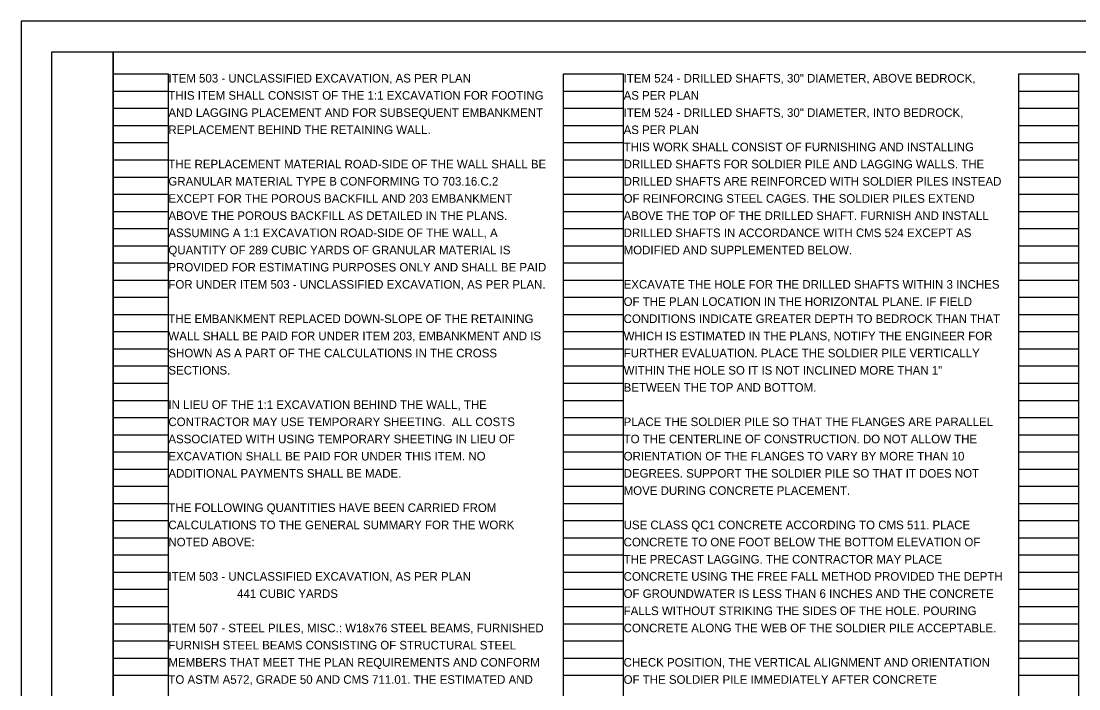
# Model space of a CAD drawing. Extents: x 0 to 34, y 0 to 22.
# Drawn here: x 0 to 17.24, y 11.12 to 22 of the extents above; entities that cross this region are included whole.
import ezdxf

# ---------------------------------------------------------------- set-up
doc = ezdxf.new("R2010")
doc.units = 0
for name, color, linetype in [('RD_P_Text', 7, 'Continuous'), ('SH_Border', 7, 'Continuous'), ('SH_Cut_Line', 7, 'Continuous'), ('SH_Data', 7, 'Continuous')]:
    doc.layers.add(name, color=color, linetype=linetype)

msp = doc.modelspace()

# ---------------------------------------------------------------- linework, layer by layer
at = {"layer": 'SH_Border'}
for points in [[(0.5, 21.5), (1.5, 21.5), (1.5, 0.5), (0.5, 0.5)], [(1.5, 21.5), (33.5, 21.5), (33.5, 0.5), (1.5, 0.5)]]:
    msp.add_lwpolyline(points, close=True, dxfattribs=at)
at = {"layer": 'SH_Cut_Line'}
msp.add_lwpolyline([(0, 0), (34, 0), (34, 22), (0, 22)], close=True, dxfattribs=at)
at = {"layer": 'SH_Data'}
for p, q in [((1.5, 0.98), (1.5, 21.14)), ((1.5, 21.14), (2.4, 21.14)), ((2.4, 0.98), (2.4, 21.14)), ((8.84, 0.98), (8.84, 21.14)), ((8.84, 21.14), (9.82, 21.14)), ((9.82, 0.98), (9.82, 21.14)), ((16.26, 0.98), (16.26, 21.14)), ((16.26, 21.14), (17.24, 21.14)), ((17.24, 0.98), (17.24, 21.14)), ((1.5, 20.86), (2.4, 20.86)), ((8.84, 20.86), (9.82, 20.86)), ((16.26, 20.86), (17.24, 20.86)), ((1.5, 20.58), (2.4, 20.58)), ((8.84, 20.58), (9.82, 20.58)), ((16.26, 20.58), (17.24, 20.58)), ((1.5, 20.3), (2.4, 20.3)), ((8.84, 20.3), (9.82, 20.3)), ((16.26, 20.3), (17.24, 20.3)), ((1.5, 20.02), (2.4, 20.02)), ((8.84, 20.02), (9.82, 20.02)), ((16.26, 20.02), (17.24, 20.02)), ((1.5, 19.74), (2.4, 19.74)), ((8.84, 19.74), (9.82, 19.74)), ((16.26, 19.74), (17.24, 19.74)), ((1.5, 19.46), (2.4, 19.46)), ((8.84, 19.46), (9.82, 19.46)), ((16.26, 19.46), (17.24, 19.46)), ((1.5, 19.18), (2.4, 19.18)), ((8.84, 19.18), (9.82, 19.18)), ((16.26, 19.18), (17.24, 19.18)), ((1.5, 18.9), (2.4, 18.9)), ((8.84, 18.9), (9.82, 18.9)), ((16.26, 18.9), (17.24, 18.9)), ((1.5, 18.62), (2.4, 18.62)), ((8.84, 18.62), (9.82, 18.62)), ((16.26, 18.62), (17.24, 18.62)), ((1.5, 18.34), (2.4, 18.34)), ((8.84, 18.34), (9.82, 18.34)), ((16.26, 18.34), (17.24, 18.34)), ((1.5, 18.06), (2.4, 18.06)), ((8.84, 18.06), (9.82, 18.06)), ((16.26, 18.06), (17.24, 18.06)), ((1.5, 17.78), (2.4, 17.78)), ((8.84, 17.78), (9.82, 17.78)), ((16.26, 17.78), (17.24, 17.78)), ((1.5, 17.5), (2.4, 17.5)), ((8.84, 17.5), (9.82, 17.5)), ((16.26, 17.5), (17.24, 17.5)), ((1.5, 17.22), (2.4, 17.22)), ((8.84, 17.22), (9.82, 17.22)), ((16.26, 17.22), (17.24, 17.22)), ((1.5, 16.94), (2.4, 16.94)), ((8.84, 16.94), (9.82, 16.94)), ((16.26, 16.94), (17.24, 16.94)), ((1.5, 16.66), (2.4, 16.66)), ((8.84, 16.66), (9.82, 16.66)), ((16.26, 16.66), (17.24, 16.66)), ((1.5, 16.38), (2.4, 16.38)), ((8.84, 16.38), (9.82, 16.38)), ((16.26, 16.38), (17.24, 16.38)), ((1.5, 16.1), (2.4, 16.1)), ((8.84, 16.1), (9.82, 16.1)), ((16.26, 16.1), (17.24, 16.1)), ((1.5, 15.82), (2.4, 15.82)), ((8.84, 15.82), (9.82, 15.82)), ((16.26, 15.82), (17.24, 15.82)), ((1.5, 15.54), (2.4, 15.54)), ((8.84, 15.54), (9.82, 15.54)), ((16.26, 15.54), (17.24, 15.54)), ((1.5, 15.26), (2.4, 15.26)), ((8.84, 15.26), (9.82, 15.26)), ((16.26, 15.26), (17.24, 15.26)), ((1.5, 14.98), (2.4, 14.98)), ((8.84, 14.98), (9.82, 14.98)), ((16.26, 14.98), (17.24, 14.98)), ((1.5, 14.7), (2.4, 14.7)), ((8.84, 14.7), (9.82, 14.7)), ((16.26, 14.7), (17.24, 14.7)), ((1.5, 14.42), (2.4, 14.42)), ((8.84, 14.42), (9.82, 14.42)), ((16.26, 14.42), (17.24, 14.42)), ((1.5, 14.14), (2.4, 14.14)), ((8.84, 14.14), (9.82, 14.14)), ((16.26, 14.14), (17.24, 14.14)), ((1.5, 13.86), (2.4, 13.86)), ((8.84, 13.86), (9.82, 13.86)), ((16.26, 13.86), (17.24, 13.86)), ((1.5, 13.58), (2.4, 13.58)), ((8.84, 13.58), (9.82, 13.58)), ((16.26, 13.58), (17.24, 13.58)), ((1.5, 13.3), (2.4, 13.3)), ((8.84, 13.3), (9.82, 13.3)), ((16.26, 13.3), (17.24, 13.3)), ((1.5, 13.02), (2.4, 13.02)), ((8.84, 13.02), (9.82, 13.02)), ((16.26, 13.02), (17.24, 13.02)), ((1.5, 12.74), (2.4, 12.74)), ((8.84, 12.74), (9.82, 12.74)), ((16.26, 12.74), (17.24, 12.74)), ((1.5, 12.46), (2.4, 12.46)), ((8.84, 12.46), (9.82, 12.46)), ((16.26, 12.46), (17.24, 12.46)), ((1.5, 12.18), (2.4, 12.18)), ((8.84, 12.18), (9.82, 12.18)), ((16.26, 12.18), (17.24, 12.18)), ((1.5, 11.9), (2.4, 11.9)), ((8.84, 11.9), (9.82, 11.9)), ((16.26, 11.9), (17.24, 11.9)), ((1.5, 11.62), (2.4, 11.62)), ((8.84, 11.62), (9.82, 11.62)), ((16.26, 11.62), (17.24, 11.62)), ((1.5, 11.34), (2.4, 11.34)), ((8.84, 11.34), (9.82, 11.34)), ((16.26, 11.34), (17.24, 11.34))]:
    msp.add_line(p, q, dxfattribs=at)

# ---------------------------------------------------------------- texts
at = {"layer": 'RD_P_Text'}
for s, p in [('ITEM 503 - UNCLASSIFIED EXCAVATION, AS PER PLAN', (2.4, 21)), ('ITEM 524 - DRILLED SHAFTS, 30" DIAMETER, ABOVE BEDROCK, ', (9.82, 21)), ('THIS ITEM SHALL CONSIST OF THE 1:1 EXCAVATION FOR FOOTING ', (2.4, 20.72)), ('AS PER PLAN', (9.82, 20.72)), ('AND LAGGING PLACEMENT AND FOR SUBSEQUENT EMBANKMENT ', (2.4, 20.44)), ('ITEM 524 - DRILLED SHAFTS, 30" DIAMETER, INTO BEDROCK, ', (9.82, 20.44)), ('REPLACEMENT BEHIND THE RETAINING WALL.', (2.4, 20.16)), ('AS PER PLAN', (9.82, 20.16)), ('THIS WORK SHALL CONSIST OF FURNISHING AND INSTALLING ', (9.82, 19.88)), ('THE REPLACEMENT MATERIAL ROAD-SIDE OF THE WALL SHALL BE ', (2.4, 19.6)), ('DRILLED SHAFTS FOR SOLDIER PILE AND LAGGING WALLS. THE ', (9.82, 19.6)), ('GRANULAR MATERIAL TYPE B CONFORMING TO 703.16.C.2 ', (2.4, 19.32)), ('DRILLED SHAFTS ARE REINFORCED WITH SOLDIER PILES INSTEAD ', (9.82, 19.32)), ('EXCEPT FOR THE POROUS BACKFILL AND 203 EMBANKMENT ', (2.4, 19.04)), ('OF REINFORCING STEEL CAGES. THE SOLDIER PILES EXTEND ', (9.82, 19.04)), ('ABOVE THE POROUS BACKFILL AS DETAILED IN THE PLANS. ', (2.4, 18.76)), ('ABOVE THE TOP OF THE DRILLED SHAFT. FURNISH AND INSTALL ', (9.82, 18.76)), ('ASSUMING A 1:1 EXCAVATION ROAD-SIDE OF THE WALL, A ', (2.4, 18.48)), ('DRILLED SHAFTS IN ACCORDANCE WITH CMS 524 EXCEPT AS ', (9.82, 18.48)), ('QUANTITY OF 289 CUBIC YARDS OF GRANULAR MATERIAL IS ', (2.4, 18.2)), ('MODIFIED AND SUPPLEMENTED BELOW.', (9.82, 18.2)), ('PROVIDED FOR ESTIMATING PURPOSES ONLY AND SHALL BE PAID ', (2.4, 17.92)), ('FOR UNDER ITEM 503 - UNCLASSIFIED EXCAVATION, AS PER PLAN.', (2.4, 17.64)), ('EXCAVATE THE HOLE FOR THE DRILLED SHAFTS WITHIN 3 INCHES ', (9.82, 17.64)), ('OF THE PLAN LOCATION IN THE HORIZONTAL PLANE. IF FIELD ', (9.82, 17.36)), ('THE EMBANKMENT REPLACED DOWN-SLOPE OF THE RETAINING ', (2.4, 17.08)), ('CONDITIONS INDICATE GREATER DEPTH TO BEDROCK THAN THAT ', (9.82, 17.08)), ('WALL SHALL BE PAID FOR UNDER ITEM 203, EMBANKMENT AND IS ', (2.4, 16.8)), ('WHICH IS ESTIMATED IN THE PLANS, NOTIFY THE ENGINEER FOR ', (9.82, 16.8)), ('SHOWN AS A PART OF THE CALCULATIONS IN THE CROSS ', (2.4, 16.52)), ('FURTHER EVALUATION. PLACE THE SOLDIER PILE VERTICALLY ', (9.82, 16.52)), ('SECTIONS.', (2.4, 16.24)), ('WITHIN THE HOLE SO IT IS NOT INCLINED MORE THAN 1" ', (9.82, 16.24)), ('BETWEEN THE TOP AND BOTTOM.', (9.82, 15.96)), ('IN LIEU OF THE 1:1 EXCAVATION BEHIND THE WALL, THE ', (2.4, 15.68)), ('CONTRACTOR MAY USE TEMPORARY SHEETING.  ALL COSTS ', (2.4, 15.4)), ('PLACE THE SOLDIER PILE SO THAT THE FLANGES ARE PARALLEL ', (9.82, 15.4)), ('ASSOCIATED WITH USING TEMPORARY SHEETING IN LIEU OF ', (2.4, 15.12)), ('TO THE CENTERLINE OF CONSTRUCTION. DO NOT ALLOW THE ', (9.82, 15.12)), ('EXCAVATION SHALL BE PAID FOR UNDER THIS ITEM. NO ', (2.4, 14.84)), ('ORIENTATION OF THE FLANGES TO VARY BY MORE THAN 10 ', (9.82, 14.84)), ('ADDITIONAL PAYMENTS SHALL BE MADE.', (2.4, 14.56)), ('DEGREES. SUPPORT THE SOLDIER PILE SO THAT IT DOES NOT ', (9.82, 14.56)), ('MOVE DURING CONCRETE PLACEMENT.', (9.82, 14.28)), ('THE FOLLOWING QUANTITIES HAVE BEEN CARRIED FROM ', (2.4, 14)), ('CALCULATIONS TO THE GENERAL SUMMARY FOR THE WORK ', (2.4, 13.72)), ('USE CLASS QC1 CONCRETE ACCORDING TO CMS 511. PLACE ', (9.82, 13.72)), ('NOTED ABOVE:', (2.4, 13.44)), ('CONCRETE TO ONE FOOT BELOW THE BOTTOM ELEVATION OF ', (9.82, 13.44)), ('THE PRECAST LAGGING. THE CONTRACTOR MAY PLACE ', (9.82, 13.16)), ('ITEM 503 - UNCLASSIFIED EXCAVATION, AS PER PLAN', (2.4, 12.88)), ('CONCRETE USING THE FREE FALL METHOD PROVIDED THE DEPTH ', (9.82, 12.88)), ('441 CUBIC YARDS', (3.52, 12.6)), ('OF GROUNDWATER IS LESS THAN 6 INCHES AND THE CONCRETE ', (9.82, 12.6)), ('FALLS WITHOUT STRIKING THE SIDES OF THE HOLE. POURING ', (9.82, 12.32)), ('ITEM 507 - STEEL PILES, MISC.: W18x76 STEEL BEAMS, FURNISHED', (2.4, 12.04)), ('CONCRETE ALONG THE WEB OF THE SOLDIER PILE ACCEPTABLE.', (9.82, 12.04)), ('FURNISH STEEL BEAMS CONSISTING OF STRUCTURAL STEEL ', (2.4, 11.76)), ('MEMBERS THAT MEET THE PLAN REQUIREMENTS AND CONFORM ', (2.4, 11.48)), ('CHECK POSITION, THE VERTICAL ALIGNMENT AND ORIENTATION ', (9.82, 11.48)), ('TO ASTM A572, GRADE 50 AND CMS 711.01. THE ESTIMATED AND ', (2.4, 11.2)), ('OF THE SOLDIER PILE IMMEDIATELY AFTER CONCRETE ', (9.82, 11.2))]:
    msp.add_text(s, height=0.14, dxfattribs=at).set_placement(p)

doc.saveas('drawing.dxf')
